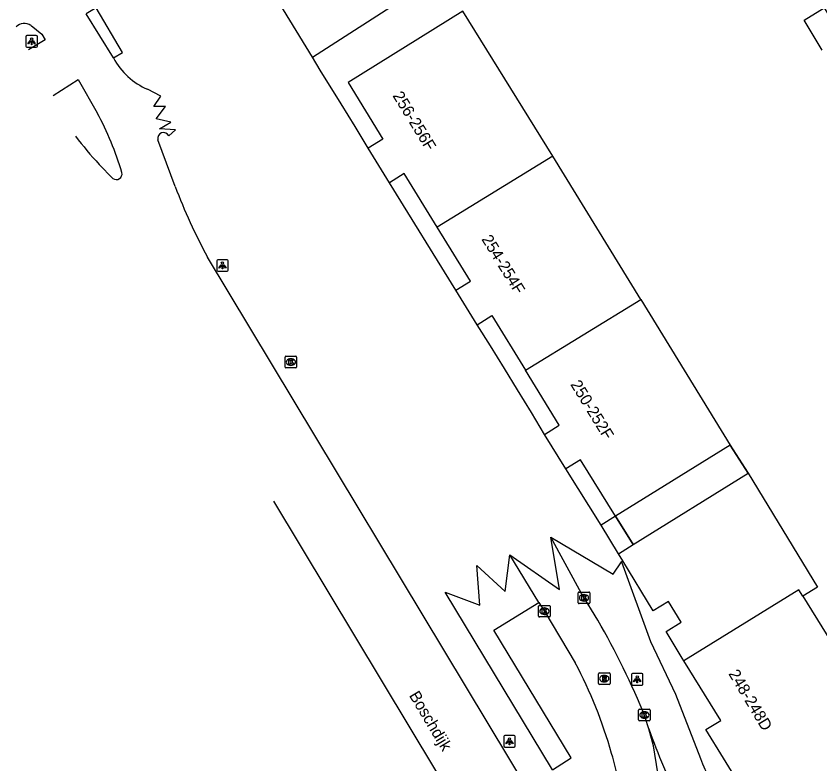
# Model space of a CAD drawing. Extents: x 160379 to 161131, y 383940 to 384849.
# Drawn here: x 160478.5 to 160548, y 384516.2 to 384580.8 of the extents above; entities that cross this region are included whole.
import ezdxf

# ---------------------------------------------------------------- set-up
doc = ezdxf.new("R2010")
doc.units = 0
for name, color, linetype in [('IMGEO_Fietspad_open', 7, 'Continuous'), ('IMGEO_Kolk', 7, 'Continuous'), ('IMGEO_Lichtpunt', 7, 'Continuous'), ('IMGEO_Muur', 7, 'Continuous'), ('IMGEO_Openbare_ruimte_label', 7, 'Continuous'), ('IMGEO_Pand', 7, 'Continuous'), ('IMGEO_Pand_nummerreeks', 7, 'Continuous'), ('IMGEO_Pand_overbouw', 7, 'Continuous'), ('IMGEO_Rijbaan_lokaal_gesloten', 7, 'Continuous'), ('IMGEO_Rijbaan_lokaal_open', 7, 'Continuous'), ('IMGEO_Rioolput', 7, 'Continuous'), ('IMGEO_Terreindeel_zand', 7, 'Continuous'), ('IMGEO_Voetpad_open', 7, 'Continuous')]:
    doc.layers.add(name, color=color, linetype=linetype)

msp = doc.modelspace()

# ---------------------------------------------------------------- linework, layer by layer
at = {"layer": 'IMGEO_Fietspad_open'}
msp.add_lwpolyline([(160486.95, 384577.153), (160487.732, 384577.633), (160485.46, 384581.497), (160484.598, 384580.955)], dxfattribs=at)
msp.add_arc((160577.661, 384534.495), 47.007, 198.94872, 207.51064, dxfattribs=at)
at = {"layer": 'IMGEO_Kolk'}
for p, q in [((160501.769, 384550.462), (160501.769, 384551.314)), ((160501.844, 384551.388), (160502.696, 384551.388)), ((160502.77, 384551.314), (160502.77, 384550.462)), ((160502.28, 384550.608), (160502.255, 384550.608)), ((160502.257, 384551.168), (160502.282, 384551.168)), ((160502.696, 384550.388), (160501.844, 384550.388)), ((160527.094, 384530.108), (160527.094, 384530.96)), ((160527.169, 384531.034), (160528.021, 384531.034)), ((160527.582, 384530.814), (160527.607, 384530.814)), ((160528.095, 384530.96), (160528.095, 384530.108)), ((160523.673, 384528.95), (160523.673, 384529.802)), ((160523.748, 384529.876), (160524.6, 384529.876)), ((160524.674, 384529.802), (160524.674, 384528.95)), ((160528.021, 384530.034), (160527.169, 384530.034)), ((160527.605, 384530.254), (160527.58, 384530.254)), ((160524.184, 384529.096), (160524.159, 384529.096)), ((160524.161, 384529.656), (160524.186, 384529.656)), ((160524.6, 384528.876), (160523.748, 384528.876)), ((160532.311, 384519.984), (160532.311, 384520.836)), ((160532.386, 384520.91), (160533.238, 384520.91)), ((160533.312, 384520.836), (160533.312, 384519.984)), ((160532.822, 384520.13), (160532.797, 384520.13)), ((160532.799, 384520.69), (160532.824, 384520.69)), ((160533.238, 384519.91), (160532.386, 384519.91))]:
    msp.add_line(p, q, dxfattribs=at)
for points in [[(160501.769, 384550.462), (160501.769, 384551.314)], [(160501.844, 384551.388), (160502.696, 384551.388)], [(160502.77, 384551.314), (160502.77, 384550.462)], [(160502.09, 384551.088), (160502.213, 384551.088), (160502.213, 384550.937), (160502.343, 384551.088), (160502.507, 384551.088), (160502.361, 384550.937), (160502.514, 384550.688), (160502.362, 384550.688), (160502.277, 384550.852), (160502.213, 384550.785), (160502.213, 384550.688), (160502.09, 384550.688), (160502.09, 384551.088)], [(160502.696, 384550.388), (160501.844, 384550.388)], [(160527.094, 384530.108), (160527.094, 384530.96)], [(160527.169, 384531.034), (160528.021, 384531.034)], [(160527.415, 384530.734), (160527.538, 384530.734), (160527.538, 384530.583), (160527.668, 384530.734), (160527.832, 384530.734), (160527.686, 384530.583), (160527.839, 384530.334), (160527.687, 384530.334), (160527.602, 384530.498), (160527.538, 384530.431), (160527.538, 384530.334), (160527.415, 384530.334), (160527.415, 384530.734)], [(160528.095, 384530.96), (160528.095, 384530.108)], [(160523.673, 384528.95), (160523.673, 384529.802)], [(160523.748, 384529.876), (160524.6, 384529.876)], [(160524.674, 384529.802), (160524.674, 384528.95)], [(160528.021, 384530.034), (160527.169, 384530.034)], [(160523.994, 384529.576), (160524.117, 384529.576), (160524.117, 384529.425), (160524.247, 384529.576), (160524.411, 384529.576), (160524.265, 384529.425), (160524.418, 384529.176), (160524.266, 384529.176), (160524.181, 384529.34), (160524.117, 384529.273), (160524.117, 384529.176), (160523.994, 384529.176), (160523.994, 384529.576)], [(160524.6, 384528.876), (160523.748, 384528.876)], [(160532.311, 384519.984), (160532.311, 384520.836)], [(160532.386, 384520.91), (160533.238, 384520.91)], [(160533.312, 384520.836), (160533.312, 384519.984)], [(160532.632, 384520.61), (160532.755, 384520.61), (160532.755, 384520.459), (160532.885, 384520.61), (160533.049, 384520.61), (160532.903, 384520.459), (160533.056, 384520.21), (160532.904, 384520.21), (160532.819, 384520.374), (160532.755, 384520.307), (160532.755, 384520.21), (160532.632, 384520.21), (160532.632, 384520.61)], [(160533.238, 384519.91), (160532.386, 384519.91)]]:
    msp.add_lwpolyline(points, dxfattribs=at)
for centre, start, end in [((160501.846, 384551.312), 91.55205, 178.44795), ((160501.846, 384551.312), 91.55205, 178.44795), ((160502.694, 384551.312), 1.55205, 88.44795), ((160502.694, 384551.312), 1.55205, 88.44795), ((160501.846, 384550.464), 181.55205, 268.44795), ((160501.846, 384550.464), 181.55205, 268.44795), ((160502.694, 384550.464), 271.55205, 358.44795), ((160502.694, 384550.464), 271.55205, 358.44795), ((160527.171, 384530.958), 91.55205, 178.44795), ((160527.171, 384530.958), 91.55205, 178.44795), ((160528.019, 384530.958), 1.55205, 88.44795), ((160528.019, 384530.958), 1.55205, 88.44795), ((160523.75, 384529.8), 91.55205, 178.44795), ((160523.75, 384529.8), 91.55205, 178.44795), ((160524.598, 384529.8), 1.55205, 88.44795), ((160524.598, 384529.8), 1.55205, 88.44795), ((160527.171, 384530.11), 181.55205, 268.44795), ((160527.171, 384530.11), 181.55205, 268.44795), ((160528.019, 384530.11), 271.55205, 358.44795), ((160528.019, 384530.11), 271.55205, 358.44795), ((160523.75, 384528.952), 181.55205, 268.44795), ((160523.75, 384528.952), 181.55205, 268.44795), ((160524.598, 384528.952), 271.55205, 358.44795), ((160524.598, 384528.952), 271.55205, 358.44795), ((160532.388, 384520.834), 91.55205, 178.44795), ((160532.388, 384520.834), 91.55205, 178.44795), ((160533.236, 384520.834), 1.55205, 88.44795), ((160533.236, 384520.834), 1.55205, 88.44795), ((160532.388, 384519.986), 181.55205, 268.44795), ((160532.388, 384519.986), 181.55205, 268.44795), ((160533.236, 384519.986), 271.55205, 358.44795), ((160533.236, 384519.986), 271.55205, 358.44795)]:
    msp.add_arc(centre, 0.0765, start, end, dxfattribs=at)
for centre, major_axis, ratio, start_param, end_param in [((160502.256, 384550.888), (-0.387, 0.002), 0.722429, 4.712389, 7.853982), ((160502.281, 384550.888), (-0.39, 0.002), 0.717154, 1.570796, 4.712389), ((160527.581, 384530.534), (-0.387, 0.002), 0.722429, 4.712389, 7.853982), ((160527.606, 384530.534), (-0.39, 0.002), 0.717154, 1.570796, 4.712389), ((160524.16, 384529.376), (-0.387, 0.002), 0.722429, 4.712389, 7.853982), ((160524.185, 384529.376), (-0.39, 0.002), 0.717154, 1.570796, 4.712389), ((160532.798, 384520.41), (-0.387, 0.002), 0.722429, 4.712389, 7.853982), ((160532.823, 384520.41), (-0.39, 0.002), 0.717154, 1.570796, 4.712389)]:
    msp.add_ellipse(centre, major_axis=major_axis, ratio=ratio, start_param=start_param, end_param=end_param, dxfattribs=at)
at = {"layer": 'IMGEO_Lichtpunt'}
for p, q in [((160480.276, 384579.083), (160479.468, 384579.083)), ((160480.276, 384579.083), (160479.468, 384579.083)), ((160479.374, 384578.988), (160479.374, 384578.181)), ((160479.374, 384578.988), (160479.374, 384578.181)), ((160480.37, 384578.181), (160480.37, 384578.988)), ((160480.37, 384578.181), (160480.37, 384578.988)), ((160479.468, 384578.087), (160480.276, 384578.087)), ((160479.468, 384578.087), (160480.276, 384578.087)), ((160495.864, 384559.639), (160495.864, 384558.832)), ((160495.864, 384559.639), (160495.864, 384558.832)), ((160496.766, 384559.734), (160495.958, 384559.734)), ((160496.766, 384559.734), (160495.958, 384559.734)), ((160496.86, 384558.832), (160496.86, 384559.639)), ((160496.86, 384558.832), (160496.86, 384559.639)), ((160495.958, 384558.738), (160496.766, 384558.738)), ((160495.958, 384558.738), (160496.766, 384558.738)), ((160531.694, 384523.902), (160531.694, 384523.095)), ((160531.694, 384523.902), (160531.694, 384523.095)), ((160532.596, 384523.997), (160531.788, 384523.997)), ((160532.596, 384523.997), (160531.788, 384523.997)), ((160532.69, 384523.095), (160532.69, 384523.902)), ((160532.69, 384523.095), (160532.69, 384523.902)), ((160531.788, 384523.001), (160532.596, 384523.001)), ((160531.788, 384523.001), (160532.596, 384523.001)), ((160521.56, 384518.641), (160520.752, 384518.641)), ((160521.56, 384518.641), (160520.752, 384518.641)), ((160520.658, 384518.546), (160520.658, 384517.739)), ((160520.658, 384518.546), (160520.658, 384517.739)), ((160521.654, 384517.739), (160521.654, 384518.546)), ((160521.654, 384517.739), (160521.654, 384518.546)), ((160520.752, 384517.645), (160521.56, 384517.645)), ((160520.752, 384517.645), (160521.56, 384517.645))]:
    msp.add_line(p, q, dxfattribs=at)
for points in [[(160479.748, 384578.652), (160479.787, 384578.624), (160479.599, 384578.362), (160479.561, 384578.389), (160479.748, 384578.652)], [(160479.85, 384578.604), (160479.897, 384578.604), (160479.897, 384578.282), (160479.85, 384578.282), (160479.85, 384578.604)], [(160479.96, 384578.624), (160479.998, 384578.651), (160480.185, 384578.389), (160480.146, 384578.361), (160479.96, 384578.624)], [(160496.238, 384559.303), (160496.277, 384559.275), (160496.089, 384559.013), (160496.051, 384559.04), (160496.238, 384559.303)], [(160496.34, 384559.255), (160496.387, 384559.255), (160496.387, 384558.933), (160496.34, 384558.933), (160496.34, 384559.255)], [(160496.45, 384559.275), (160496.488, 384559.302), (160496.675, 384559.04), (160496.636, 384559.012), (160496.45, 384559.275)], [(160532.068, 384523.566), (160532.107, 384523.538), (160531.919, 384523.276), (160531.881, 384523.303), (160532.068, 384523.566)], [(160532.17, 384523.518), (160532.217, 384523.518), (160532.217, 384523.196), (160532.17, 384523.196), (160532.17, 384523.518)], [(160532.28, 384523.538), (160532.318, 384523.565), (160532.505, 384523.303), (160532.466, 384523.275), (160532.28, 384523.538)], [(160521.032, 384518.21), (160521.071, 384518.182), (160520.883, 384517.92), (160520.845, 384517.947), (160521.032, 384518.21)], [(160521.134, 384518.162), (160521.181, 384518.162), (160521.181, 384517.84), (160521.134, 384517.84), (160521.134, 384518.162)], [(160521.244, 384518.182), (160521.282, 384518.209), (160521.469, 384517.947), (160521.43, 384517.919), (160521.244, 384518.182)]]:
    msp.add_lwpolyline(points, dxfattribs=at)
for centre in [(160479.873, 384578.786), (160496.363, 384559.437), (160532.193, 384523.7), (160521.157, 384518.344)]:
    msp.add_circle(centre, 0.0994, dxfattribs=at)
for centre, start, end in [((160479.468, 384578.988), 90, 180), ((160479.468, 384578.988), 90, 180), ((160480.276, 384578.988), 0, 90), ((160480.276, 384578.988), 0, 90), ((160479.468, 384578.181), 180, 270), ((160479.468, 384578.181), 180, 270), ((160480.276, 384578.181), 270, 0), ((160480.276, 384578.181), 270, 360), ((160495.958, 384559.639), 90, 180), ((160495.958, 384559.639), 90, 180), ((160496.766, 384559.639), 0, 90), ((160496.766, 384559.639), 0, 90), ((160495.958, 384558.832), 180, 270), ((160495.958, 384558.832), 180, 270), ((160496.766, 384558.832), 270, 0), ((160496.766, 384558.832), 270, 360), ((160531.788, 384523.902), 90, 180), ((160531.788, 384523.902), 90, 180), ((160532.596, 384523.902), 0, 90), ((160532.596, 384523.902), 0, 90), ((160531.788, 384523.095), 180, 270), ((160531.788, 384523.095), 180, 270), ((160532.596, 384523.095), 270, 0), ((160532.596, 384523.095), 270, 360), ((160520.752, 384518.546), 90, 180), ((160520.752, 384518.546), 90, 180), ((160521.56, 384518.546), 0, 90), ((160521.56, 384518.546), 0, 90), ((160520.752, 384517.739), 180, 270), ((160520.752, 384517.739), 180, 270), ((160521.56, 384517.739), 270, 0), ((160521.56, 384517.739), 270, 360)]:
    msp.add_arc(centre, 0.0946, start, end, dxfattribs=at)
at = {"layer": 'IMGEO_Muur'}
for points in [[(160507.822, 384571.227), (160506.603, 384573.183)], [(160520.732, 384550.328), (160519.516, 384552.287)], [(160523.059, 384546.528), (160521.851, 384548.487)]]:
    msp.add_lwpolyline(points, dxfattribs=at)
at = {"layer": 'IMGEO_Pand'}
for points in [[(160504.131, 384577.228), (160512.52, 384582.651), (160505.28, 384594.383), (160502.012, 384599.678)], [(160504.131, 384577.228), (160498.268, 384586.847), (160498.003, 384586.686), (160497.439, 384587.611), (160498.25, 384588.106), (160496.622, 384590.776), (160495.81, 384590.283), (160495.246, 384591.211), (160495.511, 384591.372), (160493.558, 384594.558)], [(160524.89, 384568.667), (160517.125, 384581.202), (160507.222, 384575.031), (160510.226, 384570.151), (160508.949, 384569.364)], [(160548.178, 384577.833), (160546.602, 384580.42), (160548.339, 384581.476), (160549.922, 384578.896)], [(160510.79, 384566.377), (160508.949, 384569.364)], [(160524.89, 384568.667), (160514.921, 384562.535)], [(160532.493, 384556.307), (160524.89, 384568.667)], [(160514.921, 384562.535), (160512.067, 384567.164), (160510.79, 384566.377)], [(160516.511, 384557.098), (160517.787, 384557.886), (160514.921, 384562.535)], [(160518.353, 384554.115), (160516.511, 384557.098)], [(160522.536, 384550.182), (160532.493, 384556.307)], [(160532.493, 384556.307), (160540.234, 384543.722)], [(160518.353, 384554.115), (160519.629, 384554.903), (160522.536, 384550.182)], [(160524.183, 384544.647), (160525.46, 384545.434), (160522.536, 384550.182)], [(160526.018, 384541.668), (160524.183, 384544.647)], [(160540.234, 384543.722), (160530.32, 384537.584)], [(160530.32, 384537.584), (160527.295, 384542.455), (160526.018, 384541.668)], [(160531.846, 384535.128), (160541.779, 384541.302)], [(160541.779, 384541.302), (160547.774, 384531.446), (160546.493, 384530.666)], [(160530.566, 384534.345), (160531.846, 384535.128)], [(160530.947, 384533.721), (160530.566, 384534.345)], [(160536.225, 384525.095), (160536.078, 384525.334), (160534.684, 384527.612), (160535.99, 384528.418), (160534.887, 384530.205), (160533.583, 384529.413), (160530.947, 384533.721)], [(160546.493, 384530.666), (160546.142, 384531.233), (160536.225, 384525.095)], [(160546.493, 384530.666), (160554.175, 384518.254), (160552.049, 384516.93)], [(160542.675, 384511.774), (160541.186, 384514.2), (160538.13, 384519.154), (160539.407, 384519.942), (160536.225, 384525.095)]]:
    msp.add_lwpolyline(points, dxfattribs=at)
at = {"layer": 'IMGEO_Pand_overbouw'}
msp.add_lwpolyline([(160541.779, 384541.302), (160540.234, 384543.722), (160530.32, 384537.584), (160531.846, 384535.128)], close=True, dxfattribs=at)
at = {"layer": 'IMGEO_Rijbaan_lokaal_gesloten'}
for points in [[(160486.95, 384577.153), (160484.598, 384580.955)], [(160479.821, 384579.947), (160480.755, 384579.203)], [(160480.755, 384579.203), (160481.038, 384578.726), (160479.612, 384577.847)], [(160481.745, 384573.919), (160483.902, 384575.283)], [(160483.902, 384575.283), (160485.541, 384572.423)], [(160491.737, 384570.419), (160492.305, 384570.952), (160490.926, 384571.046), (160491.898, 384571.61), (160490.644, 384571.892), (160491.427, 384572.957), (160490.425, 384572.957), (160491.051, 384573.866), (160489.897, 384574.45)], [(160492.278, 384566.053), (160490.774, 384570.091)], [(160486.885, 384566.745), (160485.704, 384567.962)], [(160522.981, 384513.599), (160495.075, 384559.958)], [(160500.777, 384538.881), (160519.448, 384507.814), (160521.23, 384504.949)]]:
    msp.add_lwpolyline(points, dxfattribs=at)
for centre, radius, start, end in [((160479.241, 384579.138), 0.995, 54.37694, 135.51374), ((160492.209, 384579.929), 5.947, 207.82503, 247.12063), ((160459.951, 384558.789), 28.995, 16.98223, 28.04782), ((160491.272, 384570.205), 0.511, 24.68159, 192.93633), ((160513.93, 384593.739), 38.225, 217.6276, 222.40379), ((160487.177, 384567.167), 0.513, 235.36144, 10.17439), ((160536.553, 384582.682), 47.295, 200.58493, 208.71592)]:
    msp.add_arc(centre, radius, start, end, dxfattribs=at)
at = {"layer": 'IMGEO_Rijbaan_lokaal_open'}
for points in [[(160540.234, 384543.722), (160541.779, 384541.302)], [(160530.32, 384537.584), (160529.073, 384536.806)], [(160531.846, 384535.128), (160530.32, 384537.584)], [(160530.566, 384534.345), (160529.073, 384536.806)], [(160521.2, 384534.243), (160525.489, 384531.265), (160524.737, 384535.778)], [(160528.778, 384528.602), (160527.371, 384530.898), (160524.737, 384535.778)], [(160523.705, 384530.142), (160521.2, 384534.243)], [(160523.705, 384530.142), (160524.204, 384529.325), (160526.839, 384524.914)], [(160533.201, 384519.231), (160532.893, 384520.207)], [(160537.326, 384506.421), (160537.094, 384506.916), (160535.638, 384509.459), (160534.052, 384512.201), (160534.462, 384512.286), (160533.987, 384515.422), (160533.605, 384517.737), (160533.201, 384519.231)]]:
    msp.add_lwpolyline(points, dxfattribs=at)
for centre, radius, start, end in [((160473.127, 384496.117), 64.438, 21.9527, 30.27297), ((160491.122, 384506.025), 40.404, 15.90734, 27.87234), ((160484.321, 384503.836), 47.545, 9.41424, 16.1979)]:
    msp.add_arc(centre, radius, start, end, dxfattribs=at)
at = {"layer": 'IMGEO_Rioolput'}
for p, q in [((160528.847, 384523.123), (160528.847, 384523.975)), ((160528.922, 384524.049), (160529.774, 384524.049)), ((160529.335, 384523.829), (160529.36, 384523.829)), ((160529.848, 384523.975), (160529.848, 384523.123)), ((160529.774, 384523.049), (160528.922, 384523.049)), ((160529.358, 384523.269), (160529.333, 384523.269))]:
    msp.add_line(p, q, dxfattribs=at)
for points in [[(160528.847, 384523.123), (160528.847, 384523.975)], [(160528.922, 384524.049), (160529.774, 384524.049)], [(160529.436, 384523.747), (160529.184, 384523.749), (160529.184, 384523.349)], [(160529.184, 384523.349), (160529.308, 384523.349), (160529.308, 384523.511), (160529.319, 384523.511)], [(160529.362, 384523.668), (160529.308, 384523.668), (160529.308, 384523.587)], [(160529.308, 384523.587), (160529.36, 384523.587)], [(160529.848, 384523.975), (160529.848, 384523.123)], [(160529.774, 384523.049), (160528.922, 384523.049)], [(160529.366, 384523.482), (160529.437, 384523.349), (160529.577, 384523.349), (160529.512, 384523.475)]]:
    msp.add_lwpolyline(points, dxfattribs=at)
for centre, radius, start, end in [((160528.924, 384523.973), 0.0765, 91.55205, 178.44795), ((160528.924, 384523.973), 0.0765, 91.55205, 178.44795), ((160529.318, 384523.458), 0.0533, 26.02933, 88.69889), ((160529.344, 384523.776), 0.19, 274.7715, 282.96867), ((160529.368, 384523.572), 0.0964, 77.00612, 93.18647), ((160529.382, 384523.629), 0.0378, 276.66336, 79.67722), ((160529.435, 384523.637), 0.109, 350.36119, 89.41601), ((160529.433, 384523.637), 0.112, 277.58423, 350.98172), ((160529.417, 384523.422), 0.108, 29.51342, 73.79051), ((160529.772, 384523.973), 0.0765, 1.55205, 88.44795), ((160529.772, 384523.973), 0.0765, 1.55205, 88.44795), ((160528.924, 384523.125), 0.0765, 181.55205, 268.44795), ((160528.924, 384523.125), 0.0765, 181.55205, 268.44795), ((160529.772, 384523.125), 0.0765, 271.55205, 358.44795), ((160529.772, 384523.125), 0.0765, 271.55205, 358.44795)]:
    msp.add_arc(centre, radius, start, end, dxfattribs=at)
for centre, major_axis, ratio, start_param, end_param in [((160529.334, 384523.549), (-0.387, 0.002), 0.722429, 4.712389, 7.853982), ((160529.359, 384523.549), (-0.39, 0.002), 0.717154, 1.570796, 4.712389)]:
    msp.add_ellipse(centre, major_axis=major_axis, ratio=ratio, start_param=start_param, end_param=end_param, dxfattribs=at)
at = {"layer": 'IMGEO_Terreindeel_zand'}
for points in [[(160508.949, 384569.364), (160507.822, 384571.227), (160506.603, 384573.183), (160504.808, 384576.111), (160504.131, 384577.228)], [(160516.511, 384557.098), (160510.79, 384566.377)], [(160524.183, 384544.647), (160523.059, 384546.528), (160521.851, 384548.487), (160520.732, 384550.328), (160519.516, 384552.287), (160518.353, 384554.115)], [(160529.073, 384536.806), (160526.018, 384541.668)], [(160530.838, 384533.648), (160530.947, 384533.721)]]:
    msp.add_lwpolyline(points, dxfattribs=at)
at = {"layer": 'IMGEO_Voetpad_open'}
for points in [[(160524.737, 384535.778), (160530.127, 384532.581), (160530.838, 384533.648)], [(160524.884, 384515.676), (160515.587, 384531.026), (160518.595, 384529.887), (160518.345, 384533.333), (160520.789, 384531.077), (160521.2, 384534.243)], [(160530.838, 384533.648), (160533.349, 384526.773), (160535.489, 384522.201), (160537.664, 384516.654)], [(160524.884, 384515.676), (160526.485, 384516.717), (160519.811, 384527.748), (160523.705, 384530.142)]]:
    msp.add_lwpolyline(points, dxfattribs=at)
msp.add_arc((160546.801, 384519.784), 9.658, 198.91269, 210.84879, dxfattribs=at)

# ---------------------------------------------------------------- texts
at = {"layer": 'IMGEO_Openbare_ruimte_label'}
msp.add_text('Boschdijk', height=1, rotation=300.92446, dxfattribs=at).set_placement((160512.45, 384522.106))
at = {"layer": 'IMGEO_Pand_nummerreeks'}
for s, rotation, p in [('256-256F', 301.54685, (160511.028, 384573.901)), ('254-254F', 301.713, (160518.702, 384561.51)), ('250-252F', 301.53539, (160526.388, 384548.963)), ('248-248D', 301.03118, (160540.043, 384523.975))]:
    msp.add_text(s, height=1, rotation=rotation, dxfattribs=at).set_placement(p)

doc.saveas('drawing.dxf')
